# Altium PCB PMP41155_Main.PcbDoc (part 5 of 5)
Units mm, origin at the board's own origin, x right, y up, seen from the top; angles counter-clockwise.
Board outline 74 x 146.5 mm, 8 copper layers (Top Layer, Signal Layer 1, Signal Layer 2, Signal Layer 3, Signal Layer 4, Signal Layer 5, Signal Layer 6, Bottom Layer), stack 1.534 mm thick; 249 components, 190 nets, 902 pads, 747 vias.
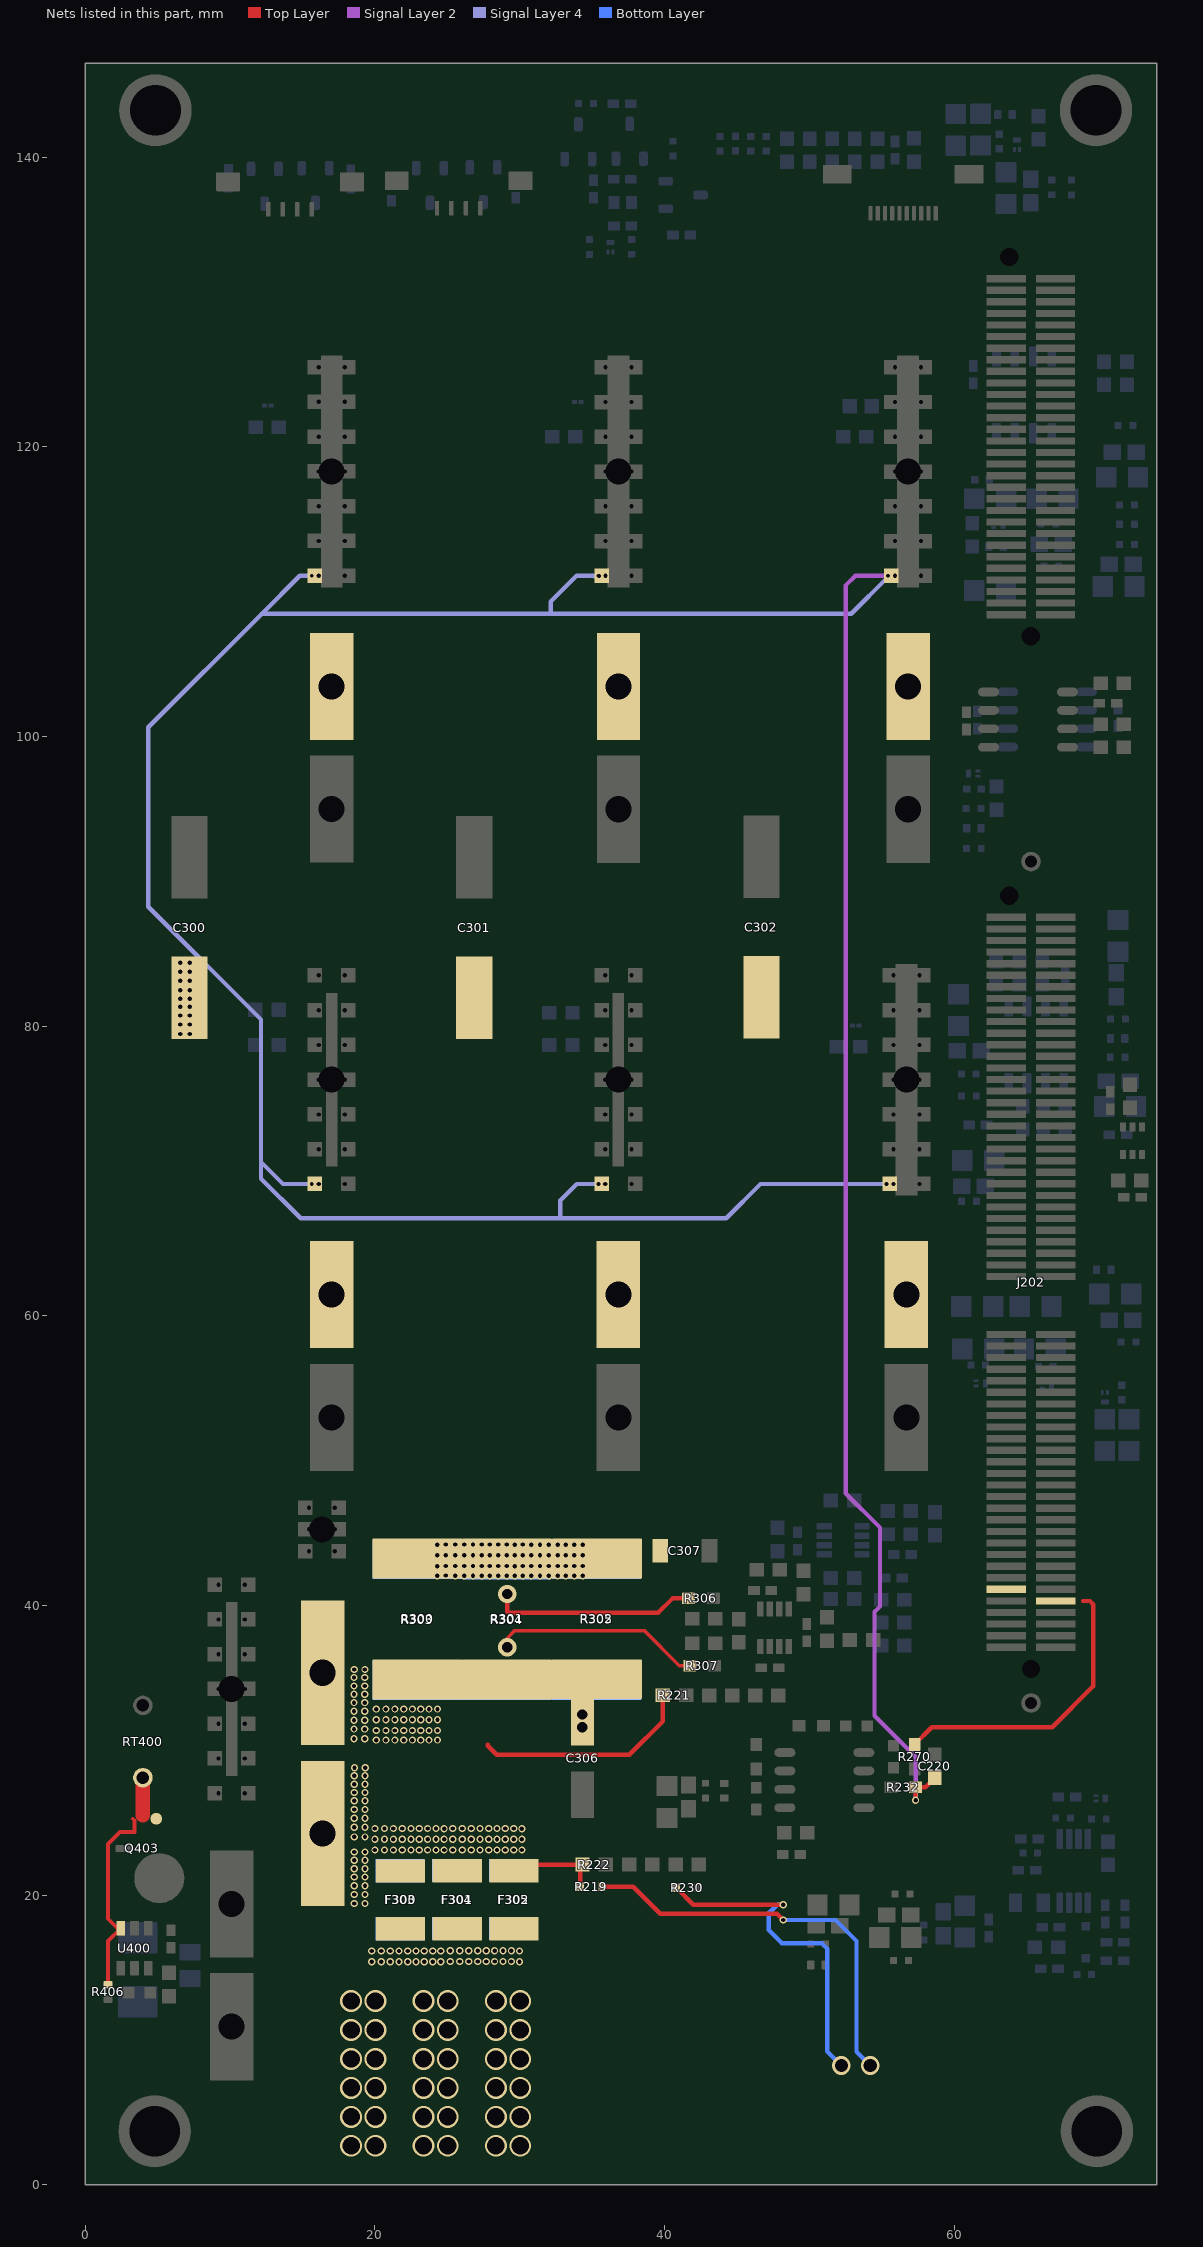
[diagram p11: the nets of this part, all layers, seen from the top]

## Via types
v1: diameter 0.5, hole 0.3, Top Layer to Bottom Layer, 533 vias
v2: diameter 0.508, hole 0.254, Top Layer to Bottom Layer, tented both sides, 102 vias
v3: diameter 1.5, hole 1.2, Top Layer to Bottom Layer, 72 vias
v4: diameter 1.3, hole 0.9, Top Layer to Bottom Layer, 30 vias
v5: diameter 1.27, hole 0.711, Top Layer to Bottom Layer, 6 vias
v6: diameter 1, hole 0.5, Top Layer to Bottom Layer, 2 vias
v7: diameter 2.49, hole 2.49, Top Layer to Bottom Layer, 2 vias

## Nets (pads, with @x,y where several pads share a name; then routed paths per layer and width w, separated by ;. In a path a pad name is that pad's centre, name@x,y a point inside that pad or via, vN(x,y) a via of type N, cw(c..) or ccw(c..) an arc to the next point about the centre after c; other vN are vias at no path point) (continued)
VBUS: F300.1 F301.1 F302.1 F303.1 F304.1 F305.1
  other v1: 19.78,15.41 20.44,15.41 21.06,15.41 21.67,15.41 22.27,15.41 22.84,15.41 23.42,15.41 24,15.41 24.56,15.4 25.21,15.42 25.87,15.42 26.49,15.42 27.1,15.42 27.7,15.42 28.27,15.42 28.85,15.42 29.43,15.42 29.99,15.41 19.78,16.15 20.44,16.15 21.06,16.15 21.67,16.15 22.27,16.15 22.84,16.15 23.42,16.15 24,16.15 24.56,16.14 29.99,16.15 25.21,16.16 25.87,16.16 26.49,16.16 27.1,16.16 27.7,16.16 28.27,16.16 28.85,16.16 29.43,16.16
  other v3: 18.36,2.69 20.04,2.69 23.36,2.69 25.04,2.69 28.36,2.69 30.04,2.69 18.36,4.69 20.04,4.69 23.36,4.69 25.04,4.69 28.36,4.69 30.04,4.69 18.36,6.69 20.04,6.69 23.36,6.69 25.04,6.69 28.36,6.69 30.04,6.69 18.36,8.69 20.04,8.69 23.36,8.69 25.04,8.69 28.36,8.69 30.04,8.69 18.36,10.69 20.04,10.69 23.36,10.69 25.04,10.69 28.36,10.69 30.04,10.69 18.36,12.69 20.04,12.69 23.36,12.69 25.04,12.69 28.36,12.69 30.04,12.69
VBUS1: C300.1 C301.1 C302.1 C307.1 pad.2@17.02,61.47 pad.2@17.02,103.47 pad.2@36.82,61.47 pad.2@36.824,103.463 pad.2@56.71,61.47 pad.2@56.818,103.465 R300.1 R301.1 R302.1 R303.1 R304.1 R305.1 R306.2 | length 14.2
  Top Layer w0.3: v5(29.138,40.793) 29.138,39.58 29.208,39.51 39.57,39.51 40.553,40.493 R306.2@41.67,40.493
  other v1: 24.306,42.064 25.546,42.064 26.166,42.064 26.776,42.064 27.376,42.064 27.946,42.064 28.526,42.064 29.106,42.064 29.666,42.054 30.206,42.064 30.79,42.057 31.41,42.057 32.02,42.057 32.62,42.057 33.19,42.057 33.77,42.057 34.35,42.057 24.886,42.074 24.306,42.724 29.666,42.724 24.886,42.734 25.546,42.734 26.166,42.734 26.776,42.734 27.376,42.734 27.946,42.734 28.526,42.734 29.106,42.734 30.206,42.734 30.79,42.727 31.41,42.727 32.02,42.727 32.62,42.727 33.19,42.727 33.77,42.727 34.35,42.727 24.306,43.464 24.886,43.474 25.546,43.474 26.166,43.474 26.776,43.474 27.376,43.474 27.946,43.474 28.526,43.474 29.106,43.474 29.666,43.464 30.206,43.474 30.79,43.467 31.41,43.467 32.02,43.467 32.62,43.467 33.19,43.467 33.77,43.467 34.35,43.467 24.306,44.204 24.886,44.214 25.546,44.214 26.166,44.214 26.776,44.214 27.376,44.214 27.946,44.214 28.526,44.214 29.106,44.214 29.666,44.204 30.206,44.214 30.79,44.207 31.41,44.207 32.02,44.207 32.62,44.207 33.19,44.207 33.77,44.207 34.35,44.207 6.56,79.464 7.22,79.464 6.56,80.124 7.23,80.124 6.56,80.744 7.23,80.744 6.56,81.354 7.23,81.354 6.57,81.908 7.23,81.908 6.56,82.488 7.22,82.488 6.56,83.148 7.23,83.148 6.56,83.768 7.23,83.768 6.56,84.378 7.23,84.378
Vbus_DAC: J202.9 R270.2 | length 20.5
  Top Layer w0.3: R270.2@57.27,30.409 58.463,31.602 66.782,31.602 69.6,34.42 69.6,40.09 69.38,40.31 68.901,40.31
VBUS_SENSE+: R219.1 | length 28.1
  Top Layer w0.3: R219.1@35.68,20.585 37.839,20.585 39.71,18.715 47.775,18.715 v1(48.2,18.29)
  Bottom Layer w0.3: v1(48.2,18.29) 51.813,18.29 53.263,16.84 53.263,12.632 53.263,11.848 53.263,10.632 53.263,9.848 53.263,9.187 v4(54.21,8.24)
VBUS_SENSE-: R230.1 | length 23.3
  Top Layer w0.3: R230.1@40.828,20.511 41.993,19.346 v1(48.21,19.346)
  Bottom Layer w0.3: v1(48.21,19.346) 47.796,19.346 47.2,18.75 47.2,17.59 48.1,16.69 50.851,16.69 51.23,16.311 51.23,9.22 v4(52.21,8.24)
VDAC_reference: J202.12
VFB: C220.1 pad.1@16.12,69.11 pad.1@16.12,111.11 pad.1@35.92,69.11 pad.1@35.924,111.103 pad.1@55.81,69.11 pad.1@55.918,111.105 R232.1 | length 244.3
  Top Layer w0.3: v1(57.34,26.56) 57.336,26.564 R232.1@57.336,27.444 58.01,27.444 C220.1@58.66,28.094
  Signal Layer 2 w0.3: v2(55.438,111.105) 53.185,111.105 52.51,110.43 52.51,47.748 54.878,45.38 54.878,39.938 54.5,39.56 54.5,32.396 57.34,29.556 v1(57.34,26.56)
  Signal Layer 4 w0.3: v2(15.64,69.11) 13.66,69.11 12.145,70.625 ; v2(15.64,111.11) 14.82,111.11 12.2,108.49 ; 35.14,111.06 35.097,111.103 33.933,111.103 32.15,109.32 32.15,108.49 ; pad.1@35.168,69.11 33.95,69.11 32.81,67.97 32.81,66.74 ; v2(55.33,69.11) 46.63,69.11 44.26,66.74 32.81,66.74 ; v2(55.438,111.105) 55.438,111.028 52.9,108.49 32.15,108.49 ; 12.145,70.625 12.145,71.375 12.145,71.51 12.145,80.463 4.35,88.258 4.35,100.64 12.2,108.49 ; 12.145,70.625 12.145,69.473 14.878,66.74 32.81,66.74 ; 12.2,108.49 32.15,108.49
  other v2: 35.44,69.11 35.444,111.103 35.474,111.087
VORING: F300.2 F301.2 F302.2 F303.2 F304.2 F305.2 pad.2@16.4,24.25 Q403.5-6-7-8 R219.2 R222.2 R406.2 RT400.2 U400.6 | length 22.5
  Top Layer w0.254: R406.2@1.58,13.82 1.58,16.835 U400.6@2.455,17.71 2.234,17.71 1.58,18.364 1.58,23.53 2.41,24.36 3.405,24.36 3.405,25.155 3.28,25.28
  Top Layer w0.3: F302.2@29.61,21.687 30.414,21.687 30.838,22.111 34.043,22.111 34.18,21.973 R219.2@34.18,20.585
  Top Layer w1: 3.98,25.53 RT400.2@3.98,28.11
  other v1: 18.584,19.424 19.324,19.424 18.584,20.044 19.324,20.044 18.584,20.654 19.324,20.654 18.584,21.254 19.324,21.254 18.584,21.824 19.324,21.824 18.584,22.404 19.324,22.404 18.584,22.984 19.324,22.984 24.784,23.114 30.154,23.114 20.004,23.124 20.664,23.124 21.284,23.124 21.894,23.124 22.494,23.124 23.064,23.124 23.644,23.124 24.224,23.124 25.374,23.124 26.034,23.124 26.654,23.124 27.264,23.124 27.864,23.124 28.434,23.124 29.014,23.124 29.594,23.124 20.004,23.864 20.664,23.864 21.284,23.864 21.894,23.864 22.494,23.864 23.064,23.864 23.644,23.864 24.224,23.864 24.784,23.854 25.374,23.864 26.034,23.864 26.654,23.864 27.264,23.864 27.864,23.864 28.434,23.864 29.014,23.864 29.594,23.864 30.154,23.854 18.584,24.024 19.324,24.024 20.004,24.604 20.664,24.604 21.284,24.604 21.894,24.604 22.494,24.604 23.064,24.604 23.644,24.604 24.224,24.604 24.784,24.594 25.374,24.604 26.034,24.604 26.654,24.604 27.264,24.604 27.864,24.604 28.434,24.604 29.014,24.604 29.594,24.604 30.154,24.594 18.584,24.684 19.324,24.684 18.584,25.304 19.324,25.304 18.584,25.914 19.324,25.914 18.584,26.514 19.324,26.514 18.584,27.084 19.324,27.084 18.584,27.664 19.324,27.664 18.584,28.244 19.324,28.244 18.594,28.804 19.334,28.804
VORING1: C306.1 pad.2@16.4,35.36 R221.2 R300.2 R301.2 R302.2 R303.2 R304.2 R305.2 R307.2 | length 29.6
  Top Layer w0.254: v5(29.138,37.118) 29.138,37.748 29.64,38.25 38.628,38.25 41.028,35.85 R307.2@41.76,35.85
  Top Layer w0.3: 27.801,30.409 27.801,30.318 28.425,29.694 37.57,29.694 39.89,32.014 R221.2@39.89,33.797
  other v1: 20.106,30.707 20.766,30.707 21.386,30.707 21.996,30.707 22.596,30.707 23.166,30.707 23.746,30.707 24.326,30.707 18.566,30.807 19.306,30.807 20.106,31.367 20.766,31.367 21.386,31.367 21.996,31.367 22.596,31.367 23.166,31.367 23.746,31.367 24.326,31.367 18.566,31.467 19.306,31.467 18.566,32.087 19.306,32.087 20.106,32.107 20.766,32.107 21.386,32.107 21.996,32.107 22.596,32.107 23.166,32.107 23.746,32.107 24.326,32.107 18.566,32.697 19.306,32.697 20.106,32.847 20.766,32.847 21.386,32.847 21.996,32.847 22.596,32.847 23.166,32.847 23.746,32.847 24.326,32.847 18.566,33.297 19.306,33.297 18.566,33.867 19.306,33.867 18.566,34.447 19.306,34.447 18.566,35.027 19.306,35.027 18.576,35.587 19.316,35.587
  other v5: 34.32,31.585 34.32,32.48
pads on no net: J200.4 J200.MP1 J200.MP2 J201.4 J201.MP1 J201.MP2 J202.1 J202.2 J202.3 J202.4 J202.5 J202.6 J202.8 J202.11 J202.13 J202.16 J202.17 J202.20 J202.29 J202.31 J202.32 J202.33 J202.41 J202.43 J202.44 J202.59 J202.60 J202.63 J202.64 J202.66 J202.67 J202.68 J202.69 J202.70 J202.72 J202.74 J202.75 J202.91 J202.92 J202.96 J202.99 J202.101 J202.113 J202.114 J202.115 J202.116 J202.117 J202.118 J202.119 J202.181 J202.182 J202.185 J202.186 J203.61 J203.62 J203.128 J203.132 J203.133 J203.136 J203.139 J203.140 J203.141 J203.142 J203.144 J203.146 J203.149 J203.164 J203.171 J203.172 J203.173 J203.174 J203.175 J203.176 J203.177 J400.MP1 J400.MP2 U401.3
copper on no net:
  other v2: 11.48,31.84 18.39,71.51 38.19,71.51 58.08,71.51 18.39,73.91 38.19,73.91 58.08,73.91 18.39,113.51 38.194,113.503 58.188,113.505 38.194,115.903 18.39,115.91 58.188,115.905
  other v7: 14.2,8.69 59.7,8.69

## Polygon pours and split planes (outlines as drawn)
VBUS1 on Top Layer "TOP_LAYER_VBUS1_P048" (solid, pour order 48): 14.24,41.043 39.46,41.043 40.98,42.562 40.98,45.26 46.24,45.26 59.15,58.17 59.15,107.66 14.84,107.66 13.69,106.51 13.69,41.593
VORING1 on Top Layer "TOP_LAYER_VORING1_P047" (solid, pour order 47): 14.615,40.52 24.231,40.52 27.801,36.95 38.32,36.95 39.198,36.072 39.198,31.775 37.507,30.084 14.493,30.084 13.77,30.807 13.77,39.675
SGND on Top Layer "TOP_LAYER_SGND_P045" (solid, pour order 45): 31.797,13.623 32.425,14.25 45.971,14.25 46.821,13.4 46.821,1.351 46.16,0.69 32.21,0.69 31.797,1.103
VBUS1 on Top Layer "TOP_LAYER_VBUS1_P034" (solid, pour order 34): 5.26,84.37 12.48,91.59 14.265,91.59 14.265,77.385 13.944,77.064 6.56,77.064 5.26,78.364
VBUS on Top Layer "TOP_LAYER_VBUS_P023" (solid, pour order 23): 16.456,16.755 18.415,18.715 31.148,18.715 31.556,18.307 31.556,1.18 31.066,0.69 17.1,0.69 16.456,1.334
VORING on Top Layer "TOP_LAYER_VORING_P010" (solid, pour order 10): 31.65,20.882 31.65,24.1 26.31,29.44 2.36,29.44 2.36,24.899 8.08,19.18 11.871,19.18 29.948,19.18
VAUX on Top Layer "TOP_LAYER_VAUX_P001" (solid, pour order 1): 3.805,23.54 11.94,23.54 12.94,22.54 12.91,22.51 12.91,15.85 12.6,15.54 7.51,15.54 7.21,15.84 7.21,18.37 6.35,19.23 2.755,19.23 2.755,22.49 2.845,22.58 3.805,22.58
VBUS1 on Bottom Layer "BOTTOM_LAYER_VBUS1_P018" (solid, pour order 18): 14.24,41.043 39.46,41.043 40.98,42.562 40.98,45.26 46.24,45.26 59.15,58.17 59.15,107.66 14.84,107.66 13.69,106.51 13.69,41.593
VORING1 on Bottom Layer "BOTTOM_LAYER_VORING1_P021" (solid, pour order 21): 14.615,40.52 19.256,40.52 22.826,36.95 38.32,36.95 39.198,36.072 39.198,31.775 37.507,30.084 14.493,30.084 13.77,30.807 13.77,39.675
SGND on Bottom Layer "BOTTOM_LAYER_SGND_P041" (solid, pour order 41): 32.02,18.247 32.619,18.846 45.84,18.846 46.453,18.233 46.453,1.822 45.42,0.79 32.647,0.79 32.02,1.417
VBUS1 on Bottom Layer "BOTTOM_LAYER_VBUS1_P039" (solid, pour order 39): 15.267,65.477 38.834,65.477 38.834,57.38 15.23,57.38 14.093,58.517 14.093,64.303
SGND on Bottom Layer "BOTTOM_LAYER_SGND_P038" (solid, pour order 38): 15.417,57.017 57.783,57.017 58.41,56.39 58.41,48.92 15.38,48.92 14.243,50.057 14.243,55.843
SGND on Bottom Layer "BOTTOM_LAYER_SGND_P037" (solid, pour order 37): 15.327,99.127 57.693,99.127 58.32,98.5 58.32,91.03 15.29,91.03 14.153,92.167 14.153,97.953
VBUS1 on Bottom Layer "BOTTOM_LAYER_VBUS1_P036" (solid, pour order 36): 15.464,107.66 57.83,107.66 58.458,107.032 58.458,99.562 15.428,99.562 14.29,100.7 14.29,106.486
VORING on Bottom Layer "BOTTOM_LAYER_VORING_P029" (solid, pour order 29): 14.446,28.676 14.98,29.21 26.49,29.21 31.6,24.1 31.6,19.18 30.85,18.43 15.3,18.43 14.446,19.284
VBUS on Bottom Layer "BOTTOM_LAYER_VBUS_P025" (solid, pour order 25): 16.437,16.774 18.396,18.733 31.13,18.733 31.537,18.326 31.537,1.199 31.047,0.709 17.081,0.709 16.437,1.353
SGND on Bottom Layer "BOTTOM_LAYER_SGND_P002" (solid, pour order 2): 2.24,14.84 11.38,14.84 11.66,14.56 11.66,7.27 11.3,6.91 2.15,6.91 1.87,7.19 1.87,14.47
VAUX on Bottom Layer "BOTTOM_LAYER_VAUX_P000" (solid, pour order 0): 3.805,23.54 11.94,23.54 12.94,22.54 12.91,22.51 12.91,15.85 12.39,15.33 2.769,15.33 1.87,16.229 1.87,21.605
SGND on Signal Layer 2 "SIGNAL_LAYER_2_SGND_P014" (solid, pour order 14): 73.39,146.5 73.39,0.69 0.17,0.69 0.17,146.5
no net on Signal Layer 2 "SIGNAL_LAYER_2_NONET_P033" (solid, pour order 33): 16.844,87.935 17.378,88.469 28.888,88.469 33.998,83.359 33.998,78.439 33.248,77.689 17.698,77.689 16.844,78.543
no net on Signal Layer 2 "SIGNAL_LAYER_2_NONET_P032" (solid, pour order 32): 16.425,85.759 16.959,86.293 28.469,86.293 33.579,81.183 33.579,76.263 32.829,75.513 17.279,75.513 16.425,76.366
no net on Signal Layer 2 "SIGNAL_LAYER_2_NONET_P031" (solid, pour order 31): 16.425,86.056 16.959,86.589 28.469,86.589 33.579,81.479 33.579,76.559 32.829,75.809 17.279,75.809 16.425,76.663
no net on Signal Layer 2 "SIGNAL_LAYER_2_NONET_P030" (solid, pour order 30): 14.355,86.319 14.889,86.853 26.399,86.853 31.509,81.743 31.509,76.823 30.759,76.073 15.209,76.073 14.355,76.926
VORING on Signal Layer 2 "SIGNAL_LAYER_2_VORING_P028" (solid, pour order 28): 14.471,28.676 15.005,29.21 26.515,29.21 31.625,24.1 31.625,19.18 30.875,18.43 15.325,18.43 14.471,19.284
VBUS on Signal Layer 2 "SIGNAL_LAYER_2_VBUS_P003" (solid, pour order 3): 16.4,16.755 17.635,17.99 30.534,17.99 31.5,17.024 31.5,1.18 31.01,0.69 17.044,0.69 16.4,1.334
VORING1 on Signal Layer 2 "SIGNAL_LAYER_2_VORING1_P007" (solid, pour order 7): 14.888,40.793 23.747,40.793 26.29,38.25 36.62,38.25 39.198,35.672 39.198,30.728 37.91,29.44 15.222,29.44 13.77,30.892 13.77,39.675
SGND on Signal Layer 3 "SIGNAL_LAYER_3_SGND_P011" (solid, pour order 11): 74.818,147.261 74.818,1.451 1.598,1.451 1.598,147.261
SGND on Signal Layer 6 "SIGNAL_LAYER_6_SGND_P012" (solid, pour order 12): 73.39,146.5 73.39,0.69 0.17,0.69 0.17,146.5
SGND on Signal Layer 1 "SIGNAL_LAYER_1_SGND_P035" (solid, pour order 35): 73.39,146.5 73.39,0.69 0.17,0.69 0.17,146.5
VBUS1 on Signal Layer 1 "SIGNAL_LAYER_1_VBUS1_P013" (solid, pour order 13): 15.112,107.419 58.572,107.419 58.572,99.511 58.343,99.282 15.114,99.282 15.112,99.28
SGND on Signal Layer 5 "SIGNAL_LAYER_5_SGND_P046" (solid, pour order 46): 31.763,13.657 32.391,14.284 45.937,14.284 46.787,13.434 46.787,1.386 46.126,0.724 32.176,0.724 31.763,1.137
VBUS1 on Signal Layer 5 "SIGNAL_LAYER_5_VBUS1_P015" (solid, pour order 15): 9.2,107.89 59.3,107.89 59.3,56.62 58.08,55.4 7.43,55.4 4.75,58.08 4.75,103.44
VORING on Signal Layer 5 "SIGNAL_LAYER_5_VORING_P027" (solid, pour order 27): 14.496,28.676 15.03,29.21 26.54,29.21 31.65,24.1 31.65,19.18 30.9,18.43 15.35,18.43 14.496,19.284
VBUS on Signal Layer 5 "SIGNAL_LAYER_5_VBUS_P024" (solid, pour order 24): 16.437,16.774 18.396,18.733 31.13,18.733 31.537,18.326 31.537,1.199 31.047,0.709 17.081,0.709 16.437,1.353
VORING1 on Signal Layer 5 "SIGNAL_LAYER_5_VORING1_P017" (solid, pour order 17): 14.871,40.52 23.5,40.52 27.864,36.156 36.936,36.156 39.198,33.895 39.198,31.775 37.507,30.084 14.843,30.084 13.965,30.962 13.965,39.614
SGND on Signal Layer 4 "SIGNAL_LAYER_4_SGND_P004" (solid, pour order 4): 31.797,13.623 32.425,14.25 45.971,14.25 46.821,13.4 46.821,1.351 46.16,0.69 32.21,0.69 31.797,1.103
VORING on Signal Layer 4 "SIGNAL_LAYER_4_VORING_P006" (solid, pour order 6): 14.496,28.676 15.03,29.21 26.54,29.21 31.65,24.1 31.65,19.18 30.9,18.43 15.35,18.43 14.496,19.284
VBUS on Signal Layer 4 "SIGNAL_LAYER_4_VBUS_P026" (solid, pour order 26): 16.437,16.774 18.396,18.733 31.13,18.733 31.537,18.326 31.537,1.199 31.047,0.709 17.081,0.709 16.437,1.353
VORING1 on Signal Layer 4 "SIGNAL_LAYER_4_VORING1_P016" (solid, pour order 16): 14.615,40.52 24.231,40.52 27.801,36.95 38.32,36.95 39.198,36.072 39.198,31.775 37.507,30.084 14.493,30.084 13.77,30.807 13.77,39.675
VORING on Signal Layer 4 "SIGNAL_LAYER_4_VORING_P020" (solid, pour order 20): 33.59,20.151 33.59,22.269 26.359,29.5 14.249,29.5 14.249,19.152 14.852,18.55 31.989,18.55
VBUS1 on Signal Layer 4 "SIGNAL_LAYER_4_VBUS1_P019" (solid, pour order 19): 15.86,39.51 43.23,39.51 59.15,55.43 59.15,107.66 7.77,107.66 3.27,103.16 3.27,52.1

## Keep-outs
Keep-Out Layer:
  text ".Layer_Name" at 1.528,-54.149 h1.52

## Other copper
Top Layer:
  text ".Layer_Name" at 1.528,-54.149 h1.52
Bottom Layer:
  text ".Layer_Name" at 1.528,-54.149 h1.52

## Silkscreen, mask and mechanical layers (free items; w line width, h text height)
Top Overlay:
  lines w0.254: 11.82,0.5 11.82,15 62.09,15 62.09,0.5 11.82,0.5 ; 239.044,3.396 292.304,3.396 292.304,19.956 239.044,19.956 239.044,3.396
  text "PMP41155_Main_Rev A" at 15.29,142.29 h4
  text ".Layer_Name" at 1.528,-54.149 h1.52
Bottom Overlay:
  text ".Layer_Name" at 1.528,-54.149 h1.52
Top Paste:
  text ".Layer_Name" at 1.528,-54.149 h1.52
Bottom Paste:
  text ".Layer_Name" at 1.528,-54.149 h1.52
Top Solder:
  text ".Layer_Name" at 1.528,-54.149 h1.52
  text ".Layer_Name" at 1.528,-54.149 h1.52
Bottom Solder:
  text ".Layer_Name" at 1.528,-54.149 h1.52
Drill Guide:
  text ".Layer_Name" at 1.528,-54.149 h1.52
M1 Board Outline:
  the board outline again, w0.178
  text ".Layer_Name" at 1.528,-54.149 h1.52
M2 Board Dimensions:
  rectangle: -9.953,-42.503 -0.428,-39.328
  rectangle: -13.128,-39.328 -9.953,-36.153
  lines w0.178: -13.128,-39.328 12.272,-39.328 ; -13.128,-36.153 -13.128,-42.503 12.272,-42.503 12.272,-36.153 ; -13.128,-4.153 12.272,-4.153 ; -9.953,-42.503 -9.953,-36.153 ; -6.778,-42.503 -6.778,-36.153 ; -0.428,-42.503 -0.428,-36.153 ; 5.922,-42.503 5.922,-36.153
  text ".Layer_Name" at 1.528,-54.149 h1.52
M3 3D STEP Top:
  text ".Layer_Name" at 1.528,-54.149 h1.52
M4 3D STEP Bottom:
  text ".Layer_Name" at 1.528,-54.149 h1.52
M5 Assembly Top:
  lines w0.254: -20.545,-55.969 147.095,-55.969 ; -20.545,-50.805 147.146,-50.805 ; -20.545,-45.64 -20.545,-61.134 81.182,-61.134 147.146,-61.134 147.146,-45.64 -20.532,-45.64 -20.532,-61.134 19.486,-61.134 ; 42.066,-61.134 42.066,-45.64 ; 74.248,-50.805 74.248,-45.64 ; 95.584,-50.805 95.584,-45.64 ; 111.383,-61.299 111.383,-56.147
  text "COMPONENTS MARKED 'DNP' SHOULD NOT BE POPULATED." at 16.171,-40.433 h1.52
  text "ASSEMBLY VARIANT:" at 16.158,-43.367 h1.52
  text ".VariantName" at 42.473,-43.367 h1.52
  text "PCB VIEWED FROM TOP SIDE" at -18.932,-48.997 h1.52
  text "BOARD #:" at 43.971,-48.997 h1.52
  text ".PRJ_Number" at 57.827,-48.997 h1.52
  text "REV:" at 79.277,-48.997 h1.52
  text ".PCB_Rev" at 86.681,-48.997 h1.52
  text "SVN REV:" at 100.562,-48.997 h1.52
  text ".VersionControl_RevNumber" at 113.415,-48.997 h1.52
  text "TID #:" at 43.971,-54.162 h1.52
  text ".TID" at 57.827,-54.162 h1.52
  text "PLOT NAME =" at -18.932,-59.377 h1.52
  text ".plot_File_Name" at 1.528,-59.377 h1.52
  text "GENERATED    :" at 44.022,-59.377 h1.52
  text ".Print_Date" at 66.107,-59.377 h1.52
  text ".Print_Time" at 84.624,-59.377 h1.52
  text "TEXAS INSTRUMENTS" at 116.742,-59.377 h1.52
M6 Assembly Bottom:
  lines w0.254: -20.557,-50.817 147.133,-50.817 ; -20.507,-55.982 147.133,-55.982 ; 15.206,-61.312 15.206,-56.16 ; 31.005,-50.817 31.005,-45.653 ; 52.341,-50.817 52.341,-45.653 ; 84.522,-61.147 84.522,-45.653 ; 107.103,-61.147 147.121,-61.147 147.121,-45.653 -20.557,-45.653 -20.557,-61.147 45.406,-61.147 147.133,-61.147 147.133,-45.653
  text "COMPONENTS MARKED 'DNP' SHOULD NOT BE POPULATED." at 141.863,-40.42 h1.52
  text ".VariantName" at 115.345,-43.367 h1.52
  text "ASSEMBLY VARIANT:" at 141.736,-43.367 h1.52
  text ".VersionControl_RevNumber" at 13.174,-49.01 h1.52
  text "SVN REV:" at 26.026,-49.01 h1.52
  text ".PCB_Rev" at 39.907,-49.01 h1.52
  text "REV:" at 47.311,-49.01 h1.52
  text ".PRJ_Number" at 68.762,-49.01 h1.52
  text "BOARD #:" at 82.617,-49.01 h1.52
  text "PCB VIEWED FROM BOTTOM SIDE" at 145.52,-49.01 h1.52
  text ".TID" at 68.762,-54.174 h1.52
  text "TID #:" at 82.617,-54.174 h1.52
  text "TEXAS INSTRUMENTS" at 9.846,-59.39 h1.52
  text ".Print_Time" at 41.965,-59.39 h1.52
  text ".Print_Date" at 60.481,-59.39 h1.52
  text "GENERATED    :" at 82.567,-59.39 h1.52
  text ".plot_File_Name" at 125.061,-59.39 h1.52
  text "PLOT NAME =" at 145.52,-59.39 h1.52
M9 Title Sheet:
  drawing of 57 lines, arcs and shapes, not listed
  text "2" at 64.084,171.789 h1.78
  text "1" at 5.664,171.784 h1.78
  text "3" at 132.283,171.784 h1.78
  text "4" at 195.952,171.784 h1.78
  text "5" at 259.427,171.784 h1.78
  text "6" at 323.054,171.784 h1.78
  text "A" at -23.707,142.752 h1.78
  text "A" at 352.213,142.752 h1.78
  text "B" at -23.707,82.3 h1.78
  text "B" at 352.213,82.3 h1.78
  text "C" at -23.707,21.975 h1.78
  text "C" at 352.213,21.975 h1.78
  text "PROJECT TITLE:" at 274.997,-25.295 h1.14
  text ".PRJ_Title" at 276.267,-28.681 h1.78
  text "DESIGNED FOR:" at 274.997,-32.94 h1.14
  text ".PRJ_Customer" at 276.267,-36.496 h1.78
  text "D" at -23.707,-38.223 h1.78
  text "D" at 352.213,-38.223 h1.78
  text "FILE NAME:" at 274.997,-40.56 h1.14
  text ".PCB_File_Name_No_Path" at 276.267,-43.608 h1.78
  text "Texas Instruments (TI) and/or its licensors do not warrant the accuracy or completeness of this specification" at 148.772,-47.719 h1.14
  text "ENGINEER:" at 274.997,-47.926 h1.14
  text "LAYOUT BY:" at 313.224,-47.926 h1.14
  text "or any information contained therein. TI and/or its licensors do not warrant that this design will meet" at 147.629,-50.58 h1.14
  text ".PRJ_Engineer" at 276.267,-51.863 h1.78
  text ".PCB_Layout" at 314.507,-51.863 h1.78
  text "the specifications, will be suitable for your application or fit for any particular purpose, or will operate in" at 147.629,-53.442 h1.14
  text ".Layer_Name" at 1.528,-54.149 h1.52
  text "ALTIUM DESIGNER VERSION:" at 313.224,-55.8 h1.14
  text "an implementation. TI and/or its licensors do not warrant that the design is production worthy. You should" at 147.629,-56.304 h1.14
  text "completely validate and test your design implementation to confirm the system functionality for your application." at 148.772,-59.165 h1.14
  text ".print_Scale" at 276.267,-59.186 h1.78
  text ".Application_BuildNumber" at 314.507,-59.186 h1.78
  text "1" at 5.664,-64.436 h1.78
  text "2" at 69.054,-64.436 h1.78
  text "3" at 132.283,-64.436 h1.78
  text "4" at 195.952,-64.436 h1.78
  text "5" at 259.427,-64.436 h1.78
  text "6" at 323.054,-64.436 h1.78
M10 Fab Notes:
  drawing of 189 lines, arcs and shapes, not listed
  text "DESIGN INFORMATION" at 301.375,129.104 h1.52
  text "MIN. TRACK WIDTH:" at 285.003,125.748 h1.52
  text "8" at 312.848,125.748 h1.52
  text "MIL" at 316.779,125.748 h1.52
  text "MIN. CLEARANCE:" at 285.003,122.595 h1.52
  text "0.2" at 311.324,122.595 h1.52
  text "mm" at 316.779,122.595 h1.52
  text "MIN. VIA PAD SIZE:" at 285.003,119.442 h1.52
  text "24" at 312.086,119.442 h1.52
  text "MIL" at 316.779,119.442 h1.52
  text "0.05mm (2MIL)" at 302.656,116.143 h1.52
  text "MINIMUM ANNULAR RING" at 276.641,115.934 h1.52
  text "EXTERNAL" at 320.64,115.934 h1.52
  text "PER" at 281.721,113.137 h1.52
  text "IPC-D-275 CLASS 2 LEVEL C" at 287.309,113.137 h1.52
  text "MIL, HOLES" at 325.11,110.584 h1.52
  text "+/-" at 315.142,110.366 h1.52
  text "+/-" at 336.833,110.366 h1.52
  text "REGISTRATION TOLERANCES:" at 276.641,110.339 h1.52
  text "METAL" at 307.115,110.339 h1.52
  text "5" at 321.751,110.339 h1.52
  text "3" at 342.909,110.339 h1.52
  text "MIL" at 345.862,110.339 h1.52
  text "HOLE SIZE TOLERANCE (UNLESS OTHERWISE SPECIFIED):" at 276.641,107.842 h1.52
  text "+/-" at 336.833,107.769 h1.52
  text "3" at 342.909,107.742 h1.52
  text "MIL" at 345.862,107.742 h1.52
  text "MATERIAL:" at 274.742,104.246 h1.52
  text "FR-4 High Tg" at 299.798,100.981 h1.52
  text "X" at 296.129,100.778 h1.52
  text "FR-408" at 285.435,100.664 h1.52
  text "OTHER" at 323.23,100.664 h1.52
  text "62 MIL (1.6mm) +/-10%" at 293.566,97.031 h1.52
  text "X" at 290.515,96.968 h1.52
  text "THICKNESS:" at 276.641,96.822 h1.52
  text "OTHER" at 326.202,96.822 h1.52
  text "TOLERANCE:" at 276.641,93.309 h1.52
  text "X" at 298.186,93.309 h1.52
  text "ANSI IPC-6012 TYPE 3 CLASS 2" at 302.708,93.309 h1.52
  text "OTHER +/-" at 302.707,89.646 h1.52
  text "BOW & TWIST:" at 276.641,85.959 h1.52
  text "X" at 298.186,85.959 h1.52
  text "ANSI IPC-6012 TYPE 3 CLASS 2" at 302.708,85.959 h1.52
  text "OTHER +/-" at 302.707,82.232 h1.52
  text "DRILLING:" at 274.742,78.915 h1.52
  text "NC_DRILL FILES" at 319.471,76.243 h1.52
  text "REFERENCE:" at 276.641,76.143 h1.52
  text "X" at 293.335,76.14 h1.52
  text "AS SHOWN" at 297.856,76.143 h1.52
  text "X" at 316.22,76.143 h1.52
  text "OTHER" at 327.04,72.53 h1.52
  text "PTH COPPER THICKNESS:" at 276.633,72.44 h1.52
  text "X" at 305.569,72.44 h1.52
  text "20-30 um" at 308.82,72.44 h1.52
  text "BOARD FINISH:" at 274.742,68.691 h1.52
  text "SILKSCREEN:" at 278.685,65.894 h1.52
  text "X" at 303.012,65.894 h1.52
  text "TOP" at 305.984,65.894 h1.52
  text "X" at 315.966,65.894 h1.52
  text "BOTTOM" at 318.963,65.894 h1.52
  text "SILKSCREEN COLOR:" at 278.685,61.952 h1.52
  text "X" at 302.987,61.952 h1.52
  text "WHITE" at 305.984,61.952 h1.52
  text "OTHER" at 318.963,61.952 h1.52
  text "X" at 306.314,58.309 h1.52
  text "GREEN" at 309.311,58.309 h1.52
  text "OTHER" at 325.008,58.309 h1.52
  text "SOLDER RESIST COLOR:" at 278.685,58.134 h1.52
  text "X" at 306.314,54.391 h1.52
  text "MATTE" at 309.311,54.391 h1.52
  text "SEMI-GLOSS" at 324.997,54.374 h1.52
  text "IMMERSION GOLD (ENIG)" at 301.691,50.002 h1.52
  text "ENEPIG" at 335.665,49.819 h1.52
  text "SURFACE FINISH:" at 274.742,49.793 h1.52
  text "X" at 297.17,49.793 h1.52
  text "IMM. TIN/SILVER OR EQUIV" at 283.112,46.306 h1.52
  text "OTHER" at 319.471,46.206 h1.52
  text "ARRAY/PANEL:" at 274.742,42.259 h1.52
  text "CUT AND TRIM PER M1 BOARD OUTLINE" at 301.691,42.05 h1.52
  text "N.C. ROUTE" at 301.691,38.597 h1.52
  text "X" at 319.167,38.597 h1.52
  text "V. SCORE" at 323.688,38.597 h1.52
  text "CERTIFICATION:" at 274.742,35.317 h1.52
  text "MATERIALS AND WORKMANSHIP FOR ALL PCBS" at 293.157,35.317 h1.52
  text "TO MEET OR EXCEED THE REQUIREMENTS OF:" at 293.157,32.928 h1.52
  text "X" at 283.95,29.66 h1.52
  text "ANSI IPC-A-600F CLASS ->" at 287.201,29.66 h1.52
  text "X" at 329.06,29.66 h1.52
  text "2" at 331.854,29.66 h1.52
  text "1" at 323.853,29.622 h1.52
  text "3" at 340.845,29.622 h1.52
  text "X" at 304.574,25.909 h1.52
  text "RoHS" at 307.825,25.909 h1.52
  text "OTHER" at 324.193,25.909 h1.52
  text "PER ORDER" at 334.279,25.909 h1.52
  text "ALL BOARDS MUST MEET OR EXCEED UL94-V0 REQUIREMENTS." at 275.441,22.002 h1.52
  text "PCB MUST BEAR THE UL94V-0 UL REGISTERED MATERIAL ID NUMBER" at 275.441,19.054 h1.52
  text "ADDITIONAL REQUIREMENTS:" at 274.742,14.751 h1.52
  text "MICROSECTION:" at 276.641,12.03 h1.52
  text "YES" at 299.647,12.03 h1.52
  text "REQUIRED" at 321.529,8.363 h1.52
  text "BARE BOARD ELEC. TEST:" at 276.641,8.291 h1.52
  text "NONE" at 309.807,8.291 h1.52
  text "X" at 318.532,8.291 h1.52
  text "PER ORDER" at 336.565,8.291 h1.52
  text "XX MIL VIAS REQUIRE NON-CONDUCTIVE FILL AND PLANARIZE" at 280.912,3.085 h1.5
  text "XX MIL VIAS REQUIRE CONDUCTIVE FILL AND PLANARIZE" at 281.115,0.444 h1.52
  text "OUTER XX MIL TRACES REQUIRE 50 OHM SINGLE-ENDED IMPEDANCE" at 281.09,-3.706 h1.47
  text "LAYER 2 & 3 (INNER LAYERS) XX MIL WIDE, XX MIL SPACE / TRACES REQUIRE 100 OHM DIFFERENTIAL IMPEDANCE" at 280.887,-9.693 h1.52
  text ".Layer_Name" at 1.528,-54.149 h1.52
M11 Gerber Information:
  lines w0.254: -20.545,-55.969 147.095,-55.969 ; -20.545,-50.805 147.146,-50.805 ; -20.545,-45.64 -20.545,-61.134 81.182,-61.134 147.146,-61.134 147.146,-45.64 -20.532,-45.64 -20.532,-61.134 19.486,-61.134 ; 42.066,-61.134 42.066,-45.64 ; 74.248,-50.805 74.248,-45.64 ; 95.584,-50.805 95.584,-45.64 ; 111.383,-61.299 111.383,-56.147
  text "ALL ARTWORK VIEWED FROM TOP SIDE" at -18.932,-48.997 h1.52
  text "BOARD #:" at 43.971,-48.997 h1.52
  text ".PRJ_Number" at 57.827,-48.997 h1.52
  text "REV:" at 79.277,-48.997 h1.52
  text ".PCB_Rev" at 86.681,-48.997 h1.52
  text "SVN REV:" at 100.562,-48.997 h1.52
  text ".VersionControl_RevNumber" at 113.415,-48.997 h1.52
  text "LAYER NAME =" at -18.932,-54.149 h1.52
  text "TID #:" at 43.971,-54.162 h1.52
  text ".TID" at 57.827,-54.162 h1.52
  text "PLOT NAME =" at -18.932,-59.377 h1.52
  text ".plot_File_Name" at 1.528,-59.377 h1.52
  text "GENERATED    :" at 44.022,-59.377 h1.52
  text ".Print_Date" at 66.107,-59.377 h1.52
  text ".Print_Time" at 84.624,-59.377 h1.52
  text "TEXAS INSTRUMENTS" at 116.742,-59.377 h1.52
M12 Stackup:
  text ".Layer_Name" at 1.528,-54.149 h1.52
M13 Component Bodies Top:
  text ".Layer_Name" at 1.528,-54.149 h1.52
M14 Component Bodies Bottom:
  text ".Layer_Name" at 1.528,-54.149 h1.52
M15 Courtyards Top:
  text ".Layer_Name" at 1.528,-54.149 h1.52
M16 Courtyards Bottom:
  text ".Layer_Name" at 1.528,-54.149 h1.52
Drill Drawing:
  text ".Layer_Name" at 1.528,-54.149 h1.52
M17 Embedded Cavity:
  text ".Layer_Name" at 1.528,-54.149 h1.52
M18 Embedded Assembly:
  text ".Layer_Name" at 1.528,-54.149 h1.52
M19 Embedded Keepout:
  text ".Layer_Name" at 1.528,-54.149 h1.52

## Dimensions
-13.128,-42.503 to 12.272,-42.503 on M2 Board Dimensions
